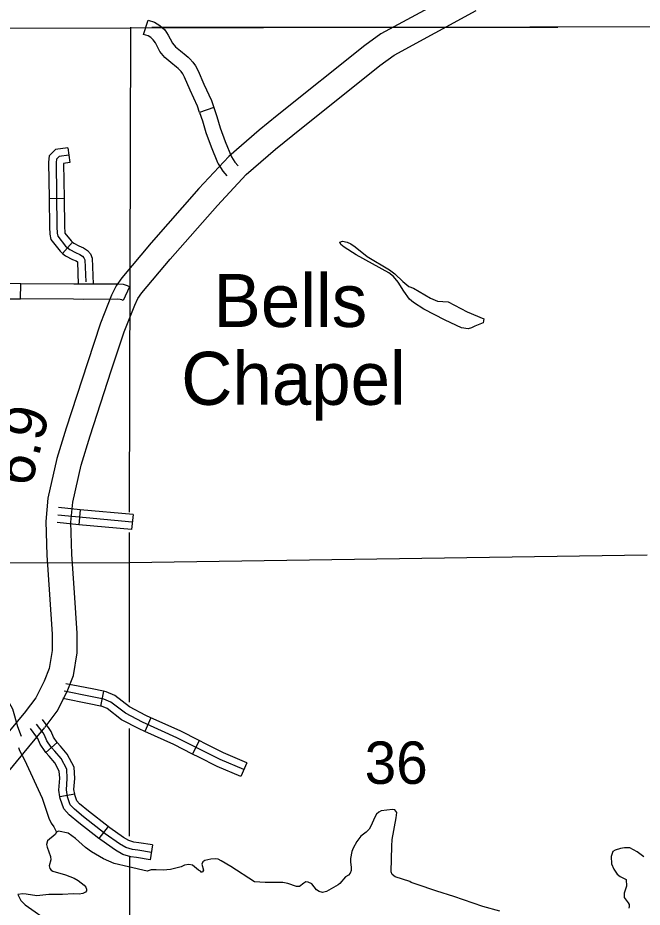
# Model space of a CAD drawing. Extents: x 1374139 to 1377472, y 1168351 to 1170484.
# Drawn here: x 1376217.1 to 1376341.5, y 1168808.4 to 1168985.6 of the extents above; entities that cross this region are included whole.
import ezdxf

# ---------------------------------------------------------------- set-up
doc = ezdxf.new("R2010")
doc.units = 0
doc.layers.add('Default', color=7, linetype='Continuous')

msp = doc.modelspace()

# ---------------------------------------------------------------- linework, layer by layer
at = {"layer": 'Default'}
for p, q in [((1376186.66, 1168983.45), (1376558.09, 1168984.42)), ((1376242.11, 1168982.29), (1376243.07, 1168985.14)), ((1376256.14, 1168967.73), (1376253.3, 1168966.75)), ((1376227.08, 1168959.7), (1376227.48, 1168956.73)), ((1376223.32, 1168949.58), (1376226.32, 1168949.62)), ((1376226.03, 1168938.63), (1376227.98, 1168940.91)), ((1376217.65, 1168929.58), (1376217.67, 1168932.58)), ((1376239.34, 1168931.98), (1376238.08, 1168929.26)), ((1376229.53, 1168887.58), (1376229.25, 1168884.59)), ((1376240.05, 1168886.6), (1376239.77, 1168883.61)), ((1376234.18, 1168851.39), (1376233.6, 1168848.45)), ((1376243.62, 1168846.1), (1376242.39, 1168843.37)), ((1376224.94, 1168841.16), (1376222.71, 1168839.17)), ((1376253.23, 1168841.56), (1376251.87, 1168838.89)), ((1376262.71, 1168837.16), (1376261.53, 1168834.4)), ((1376228.44, 1168830.86), (1376225.48, 1168830.37)), ((1376235.09, 1168824.44), (1376233.24, 1168822.08)), ((1376243.94, 1168820.77), (1376243.45, 1168817.81)), ((1376239.32, 1168816.56), (1376239.34, 1168783.09))]:
    msp.add_line(p, q, dxfattribs=at)
for points in [[(1376305.8, 1168991.31), (1376289.45, 1168982.4), (1376286.22, 1168980.09), (1376268.74, 1168966.09), (1376265.2, 1168963.23), (1376259.12, 1168957.94), (1376253.16, 1168951.57), (1376243.64, 1168940.74), (1376237.79, 1168933.8), (1376236.69, 1168932.18), (1376235.79, 1168930.31), (1376233.59, 1168924.74), (1376230.96, 1168916.81), (1376226.73, 1168903.8), (1376224.9, 1168897.77), (1376223.09, 1168889.89), (1376222.66, 1168885.22), (1376222.87, 1168878.49), (1376223.39, 1168870.7), (1376223.91, 1168862.76), (1376223.94, 1168859.49), (1376223.32, 1168855.91), (1376222.33, 1168853.38), (1376220.68, 1168850.08), (1376218.57, 1168847.29)], [(1376222.56, 1168844.27), (1376224.95, 1168847.43), (1376226.9, 1168851.34), (1376228.16, 1168854.56), (1376228.94, 1168859.08), (1376228.91, 1168862.94), (1376228.38, 1168871.03), (1376227.86, 1168878.74), (1376227.67, 1168885.07), (1376228.04, 1168889.1), (1376229.73, 1168896.48), (1376231.5, 1168902.3), (1376235.71, 1168915.26), (1376238.29, 1168923.03), (1376240.38, 1168928.3), (1376241.03, 1168929.68), (1376241.78, 1168930.77), (1376247.43, 1168937.48), (1376256.86, 1168948.21), (1376262.6, 1168954.34), (1376268.42, 1168959.4), (1376271.88, 1168962.2), (1376289.24, 1168976.1), (1376292.11, 1168978.15), (1376308.41, 1168987.05)], [(1376243.07, 1168985.14), (1376244.32, 1168984.72), (1376245.41, 1168984.06), (1376246.36, 1168983.16), (1376247.08, 1168982.14), (1376247.44, 1168981.43), (1376247.92, 1168980.54), (1376248.52, 1168979.81), (1376249.51, 1168978.98), (1376250.65, 1168978.07), (1376251.03, 1168977.74)], [(1376239.54, 1168983.71), (1376239.29, 1168887.07)], [(1376243.77, 1168983.72), (1376324.67, 1168983.74)], [(1376249.05, 1168975.49), (1376248.73, 1168975.77), (1376247.61, 1168976.66), (1376246.39, 1168977.68), (1376245.42, 1168978.85), (1376244.78, 1168980.04), (1376244.5, 1168980.59), (1376244.08, 1168981.19), (1376243.59, 1168981.66), (1376243.06, 1168981.98), (1376242.11, 1168982.29)], [(1376251.03, 1168977.74), (1376251.4, 1168977.42), (1376251.98, 1168976.74), (1376252.53, 1168976.01), (1376253, 1168975.02), (1376254.18, 1168972.39), (1376255.67, 1168969.09), (1376256.14, 1168967.73)], [(1376253.3, 1168966.75), (1376252.88, 1168967.98), (1376251.45, 1168971.16), (1376250.28, 1168973.76), (1376249.95, 1168974.45), (1376249.64, 1168974.86), (1376249.26, 1168975.3), (1376249.05, 1168975.49)], [(1376253.3, 1168966.75), (1376253.89, 1168965.05), (1376254.56, 1168962.75), (1376255.59, 1168959.87), (1376256.91, 1168956.73)], [(1376256.14, 1168967.73), (1376256.75, 1168965.95), (1376257.41, 1168963.67), (1376258.39, 1168960.96), (1376259.67, 1168957.89)], [(1376227.08, 1168959.7), (1376224.61, 1168959.37), (1376223.33, 1168958.09), (1376223.22, 1168956.83), (1376223.32, 1168949.58)], [(1376227.28, 1168958.21), (1376225.31, 1168957.95), (1376224.78, 1168957.42), (1376224.72, 1168956.77), (1376224.9, 1168943.95), (1376224.96, 1168942.65), (1376225.07, 1168942.06), (1376226.61, 1168940.11), (1376227.44, 1168939.4), (1376228.62, 1168938.81), (1376229.44, 1168938.45), (1376229.97, 1168938.1), (1376230.27, 1168937.75), (1376230.45, 1168937.33), (1376230.63, 1168932.95)], [(1376259.67, 1168957.89), (1376259.69, 1168957.86), (1376260.33, 1168956.82), (1376260.99, 1168956.07)], [(1376227.48, 1168956.73), (1376226.22, 1168956.56), (1376226.32, 1168949.62)], [(1376256.91, 1168956.73), (1376257.02, 1168956.48), (1376257.92, 1168955.03), (1376258.74, 1168954.09)], [(1376223.32, 1168949.58), (1376223.4, 1168943.9), (1376223.46, 1168942.47), (1376223.67, 1168941.41), (1376225.52, 1168939.07), (1376226.03, 1168938.63)], [(1376226.32, 1168949.62), (1376226.4, 1168943.99), (1376226.45, 1168942.83), (1376226.47, 1168942.7), (1376227.7, 1168941.15), (1376227.98, 1168940.91)], [(1376227.98, 1168940.91), (1376228.27, 1168940.66), (1376229.25, 1168940.17), (1376230.16, 1168939.78), (1376230.99, 1168939.23), (1376231.56, 1168938.54), (1376231.93, 1168937.67), (1376232.14, 1168932.5)], [(1376302.83, 1168928.98), (1376306.64, 1168926.99), (1376309.94, 1168925.62), (1376309.84, 1168924.84), (1376308.13, 1168924.15), (1376307.52, 1168923.81), (1376306.8, 1168923.61), (1376305.52, 1168923.79), (1376302.21, 1168925.34), (1376297.97, 1168927.56), (1376295.94, 1168928.86), (1376295.14, 1168929.54), (1376294.01, 1168931.11), (1376292.9, 1168932.88), (1376291.95, 1168934.01), (1376290.99, 1168934.79), (1376284.49, 1168938.38), (1376282.12, 1168939.9), (1376281.45, 1168940.44), (1376281.27, 1168940.9), (1376281.77, 1168941.07), (1376282.71, 1168940.86), (1376283.44, 1168940.52), (1376284.34, 1168939.94), (1376286.69, 1168938.03), (1376291.17, 1168935.35), (1376292.23, 1168934.54), (1376293.79, 1168933.07), (1376295.02, 1168932.08), (1376295.91, 1168931.74), (1376299.31, 1168929.74), (1376300.74, 1168929.12)], [(1376226.03, 1168938.63), (1376226.6, 1168938.14), (1376227.98, 1168937.45), (1376228.73, 1168937.13), (1376228.96, 1168936.97), (1376229.14, 1168932.48)], [(1376217.67, 1168932.58), (1376211.21, 1168932.62), (1376207.08, 1168932.56)], [(1376228.23, 1168932.5), (1376217.67, 1168932.58)], [(1376239.34, 1168931.98), (1376238.97, 1168932.15), (1376238.15, 1168932.44), (1376237, 1168932.53), (1376230.28, 1168932.49), (1376228.23, 1168932.5)], [(1376207.13, 1168929.56), (1376211.22, 1168929.62), (1376217.65, 1168929.58)], [(1376228.21, 1168929.5), (1376217.65, 1168929.58)], [(1376238.08, 1168929.26), (1376237.84, 1168929.37), (1376237.52, 1168929.48), (1376236.89, 1168929.53), (1376230.28, 1168929.49), (1376228.21, 1168929.5)], [(1376300.74, 1168929.12), (1376302.83, 1168928.98)], [(1376229.53, 1168887.58), (1376225.21, 1168887.98)], [(1376240.05, 1168886.6), (1376229.53, 1168887.58)], [(1376239.91, 1168885.1), (1376225.07, 1168886.49)], [(1376229.25, 1168884.59), (1376224.93, 1168884.99)], [(1376239.77, 1168883.61), (1376229.25, 1168884.59)], [(1376239.28, 1168883.06), (1376239.27, 1168876.97)], [(1376342.46, 1168878.54), (1376239.27, 1168876.97)], [(1376239.27, 1168876.97), (1376185.15, 1168876.94)], [(1376239.27, 1168876.97), (1376239.29, 1168849.24)], [(1376209.24, 1168859.91), (1376209.41, 1168856.76), (1376209.66, 1168855.53), (1376210.03, 1168853.96), (1376211.48, 1168853), (1376212.46, 1168852.74), (1376213.48, 1168851.91), (1376214.2, 1168851.19), (1376216.04, 1168847.92), (1376217.04, 1168844.36), (1376217.78, 1168842.47)], [(1376234.18, 1168851.39), (1376231.89, 1168851.85), (1376226.65, 1168852.89)], [(1376233.6, 1168848.45), (1376231.3, 1168848.91), (1376226.07, 1168849.95)], [(1376262.12, 1168835.78), (1376257.43, 1168837.79), (1376253.8, 1168839.59), (1376248.81, 1168842.13), (1376241.91, 1168845.23), (1376238.54, 1168847), (1376235.65, 1168849.24), (1376234.25, 1168849.85), (1376231.59, 1168850.38), (1376226.36, 1168851.42)], [(1376243.62, 1168846.1), (1376242.57, 1168846.58), (1376239.36, 1168848.27), (1376236.42, 1168850.55), (1376234.7, 1168851.29), (1376234.18, 1168851.39)], [(1376242.39, 1168843.37), (1376241.25, 1168843.88), (1376237.73, 1168845.73), (1376234.88, 1168847.94), (1376233.8, 1168848.41), (1376233.6, 1168848.45)], [(1376218.63, 1168847.37), (1376215.46, 1168843.5), (1376209.92, 1168836.83), (1376208.28, 1168834.88)], [(1376243.7, 1168819.29), (1376240.98, 1168819.73), (1376239.92, 1168819.88), (1376238.62, 1168820.24), (1376237.35, 1168821), (1376234.52, 1168822.98), (1376230.21, 1168826.35), (1376228.36, 1168827.88), (1376227.56, 1168828.75), (1376227, 1168830.39), (1376226.77, 1168831.77), (1376226.95, 1168834.04), (1376226.83, 1168835.87), (1376225.71, 1168838), (1376224.47, 1168839.44), (1376223.73, 1168840.27), (1376222.9, 1168841.54), (1376222.43, 1168842.66), (1376222.13, 1168843.1), (1376220.84, 1168844.86)], [(1376224.94, 1168841.16), (1376224.93, 1168841.18), (1376224.23, 1168842.25), (1376223.76, 1168843.38), (1376223.36, 1168843.97), (1376222.04, 1168845.75)], [(1376253.23, 1168841.56), (1376249.46, 1168843.48), (1376243.62, 1168846.1)], [(1376212.11, 1168831.67), (1376213.76, 1168833.62), (1376219.32, 1168840.31), (1376222.5, 1168844.2)], [(1376222.71, 1168839.17), (1376222.54, 1168839.36), (1376221.57, 1168840.83), (1376221.11, 1168841.95), (1376220.91, 1168842.24), (1376219.63, 1168843.97)], [(1376239.29, 1168844), (1376239.31, 1168822.54)], [(1376251.87, 1168838.89), (1376248.17, 1168840.78), (1376242.39, 1168843.37)], [(1376228.44, 1168830.86), (1376228.28, 1168831.83), (1376228.45, 1168834.03), (1376228.31, 1168836.29), (1376226.96, 1168838.85), (1376225.6, 1168840.43), (1376224.94, 1168841.16)], [(1376262.71, 1168837.16), (1376258.06, 1168839.15), (1376254.48, 1168840.93), (1376253.23, 1168841.56)], [(1376217.21, 1168840.16), (1376217.42, 1168839.62), (1376218.43, 1168837.71), (1376221.97, 1168830.1), (1376223.25, 1168826.11), (1376223.72, 1168825.08), (1376224.28, 1168824.41)], [(1376225.48, 1168830.37), (1376225.26, 1168831.7), (1376225.44, 1168834.05), (1376225.35, 1168835.45), (1376224.46, 1168837.15), (1376223.34, 1168838.46), (1376222.71, 1168839.17)], [(1376261.53, 1168834.4), (1376256.8, 1168836.43), (1376253.13, 1168838.25), (1376251.87, 1168838.89)], [(1376233.24, 1168822.08), (1376229.27, 1168825.18), (1376227.32, 1168826.79), (1376226.24, 1168827.97), (1376225.54, 1168830.02), (1376225.48, 1168830.37)], [(1376235.09, 1168824.44), (1376231.15, 1168827.52), (1376229.39, 1168828.97), (1376228.88, 1168829.53), (1376228.46, 1168830.75), (1376228.44, 1168830.86)], [(1376291.63, 1168820.55), (1376291.71, 1168821.88), (1376292.51, 1168826.19), (1376292.58, 1168827.25), (1376292.22, 1168827.77), (1376291.76, 1168827.83), (1376289.51, 1168827.59), (1376289.02, 1168827.33), (1376288.57, 1168826.92), (1376288.17, 1168826.2), (1376287.52, 1168824.62), (1376287.12, 1168823.93), (1376286.48, 1168823.29), (1376285.44, 1168822.5), (1376284.65, 1168821.45), (1376283.91, 1168820.11), (1376283.65, 1168819.46), (1376283.37, 1168818.09), (1376283.35, 1168817.38), (1376283.52, 1168816.27), (1376283.52, 1168815.69), (1376283.33, 1168815.12), (1376282.95, 1168814.73), (1376282.38, 1168814.39), (1376281.27, 1168813.12), (1376280.9, 1168812.82), (1376278.62, 1168811.49), (1376277.81, 1168811.33), (1376277.12, 1168811.51), (1376276.63, 1168811.8), (1376275.68, 1168813.05), (1376274.97, 1168813.33), (1376274.47, 1168813.42), (1376274.06, 1168813.18), (1376273.2, 1168812.46), (1376272.6, 1168812.46), (1376270.88, 1168813.07), (1376269.89, 1168813.32), (1376266.4, 1168813.26), (1376264.23, 1168813.42), (1376259.53, 1168816.51), (1376257.62, 1168817.63), (1376256.99, 1168817.92), (1376256.53, 1168817.98), (1376255.53, 1168817.91), (1376254.36, 1168817.66), (1376253.96, 1168817.39), (1376253.76, 1168816.94), (1376254.07, 1168815.73), (1376253.92, 1168815.44), (1376253.74, 1168815.38), (1376253.62, 1168815.37), (1376253.5, 1168815.57), (1376253.09, 1168815.74), (1376251.92, 1168816.73), (1376251.2, 1168816.86), (1376250.34, 1168816.76), (1376249.64, 1168816.4), (1376247.49, 1168815.85), (1376246.04, 1168815.73), (1376244.66, 1168815.79)], [(1376244.66, 1168815.79), (1376243.68, 1168815.8), (1376242.84, 1168815.58), (1376239.18, 1168816.41), (1376236.28, 1168817.05), (1376234.18, 1168818.01), (1376231.78, 1168819.42), (1376230.61, 1168820.27), (1376228.56, 1168822.09), (1376227.15, 1168823.11), (1376225.2, 1168823.5), (1376224.81, 1168823.35), (1376224.56, 1168822.88), (1376223.02, 1168821.59), (1376222.82, 1168820.84), (1376222.92, 1168820.3), (1376223.63, 1168818.44), (1376223.65, 1168817.82), (1376223.36, 1168816.61), (1376223.48, 1168816.11), (1376223.77, 1168815.74), (1376224.05, 1168815.57), (1376226.59, 1168814.82), (1376228.33, 1168814.15), (1376229.14, 1168813.69), (1376230.29, 1168812.77), (1376230.64, 1168812.35), (1376230.77, 1168811.94), (1376230.76, 1168811.64), (1376230.57, 1168811.39), (1376230.08, 1168811.12), (1376229.3, 1168810.97), (1376228.16, 1168811.06), (1376226.03, 1168810.9), (1376223.29, 1168810.88), (1376220.9, 1168810.63), (1376218.73, 1168810.98), (1376218.09, 1168811.03), (1376217.09, 1168810.9), (1376217.73, 1168809.69), (1376218.55, 1168808.85), (1376223.69, 1168805.22)], [(1376224.28, 1168824.41), (1376224.81, 1168823.35)], [(1376243.94, 1168820.77), (1376241.2, 1168821.22), (1376240.22, 1168821.35), (1376239.22, 1168821.63), (1376238.17, 1168822.26), (1376235.41, 1168824.19), (1376235.09, 1168824.44)], [(1376243.45, 1168817.81), (1376240.76, 1168818.25), (1376239.62, 1168818.41), (1376238.02, 1168818.84), (1376236.53, 1168819.75), (1376233.63, 1168821.78), (1376233.24, 1168822.08)], [(1376313.16, 1168807.6), (1376309.75, 1168808.52), (1376303.94, 1168810.53), (1376300.61, 1168811.54), (1376296.49, 1168812.94), (1376295.44, 1168813.31), (1376295.19, 1168813.52), (1376292.25, 1168814.42), (1376291.7, 1168814.9), (1376291.5, 1168815.42), (1376291.63, 1168820.55)], [(1376341.85, 1168818.42), (1376340.52, 1168819.42), (1376339.06, 1168820.22), (1376338, 1168820.23), (1376337.18, 1168820.04), (1376336.11, 1168819.71), (1376335.68, 1168819.44), (1376335.29, 1168818.5), (1376335.37, 1168817.02), (1376335.84, 1168815.94), (1376336.51, 1168814.97), (1376337.08, 1168814.51), (1376338.28, 1168813.9), (1376338.36, 1168812.56), (1376337.94, 1168811.15), (1376337.88, 1168810.32), (1376338.71, 1168809.25), (1376338.87, 1168808.89), (1376338.88, 1168808.51), (1376338.83, 1168808.17)], [(1376239.32, 1168818.44), (1376239.32, 1168816.56)]]:
    msp.add_lwpolyline(points, dxfattribs=at)

# ---------------------------------------------------------------- texts
for s, height, p in [('Bells', 10.56, (1376256.1, 1168923.98)), ('Chapel', 10.56, (1376249.65, 1168908.47)), ('36', 8.448, (1376286.2, 1168832.94))]:
    msp.add_text(s, height=height, dxfattribs=at).set_placement(p)
msp.add_text('6.9', height=8.448, rotation=75.9214, dxfattribs=at).set_placement((1376219.7, 1168891.8))

doc.saveas('drawing.dxf')
